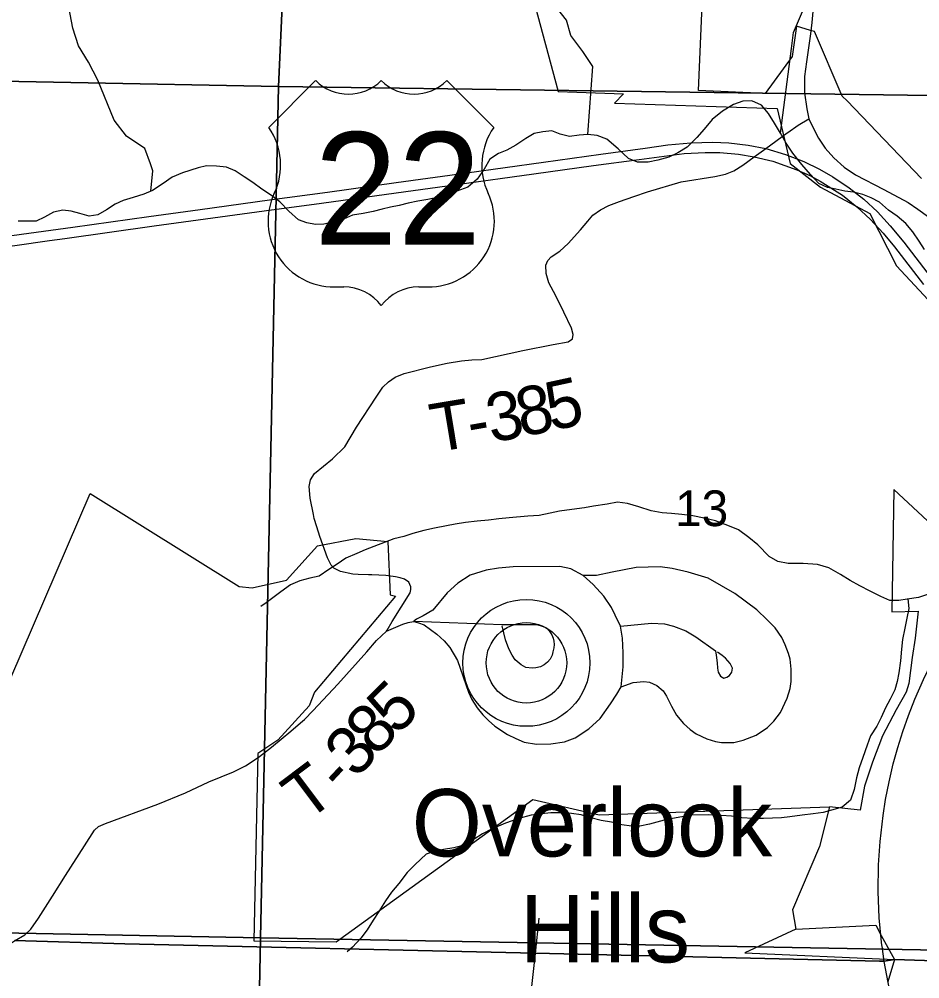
# Model space of a CAD drawing. Extents: x -19 to 40.8, y -1.8 to 26.1.
# Drawn here: x 7.005 to 8.061, y 15.876 to 17.001 of the extents above; entities that cross this region are included whole.
import ezdxf

# ---------------------------------------------------------------- set-up
doc = ezdxf.new("R2010")
doc.units = 0
for name, color, linetype in [('Default', 7, 'Continuous'), ('GM_X_City_Street', 7, 'Continuous'), ('GM_X_Corporation', 7, 'Continuous'), ('GM_X_Corporation_Text', 7, 'Continuous'), ('GM_X_Major_River', 7, 'Continuous'), ('GM_X_Rail_Line_Text', 7, 'Continuous'), ('GM_X_Section', 7, 'Continuous'), ('GM_X_Section_Text', 7, 'Continuous'), ('GM_X_State_Route', 7, 'Continuous'), ('GM_X_State_Shield', 7, 'Continuous'), ('GM_X_Township_Road', 7, 'Continuous'), ('GM_X_Township_Road_Text', 7, 'Continuous'), ('GM_X_Unincorporated', 7, 'Continuous'), ('GM_X_Unincorporated_Location', 7, 'Continuous'), ('RW_P_Text', 7, 'Continuous')]:
    doc.layers.add(name, color=color, linetype=linetype)

msp = doc.modelspace()

# ---------------------------------------------------------------- linework, layer by layer
at = {"layer": 'Default'}
for p, q in [((7.5751, 17.147), (7.6369, 16.9157)), ((7.8016, 16.917), (7.8065, 17.0357)), ((7.9164, 16.9926), (7.9112, 16.957)), ((7.9326, 16.9875), (7.9164, 16.9926)), ((7.9375, 16.986), (7.9326, 16.9875)), ((7.9699, 16.9105), (7.9375, 16.986)), ((7.9112, 16.957), (7.8798, 16.9137)), ((7.6369, 16.9157), (7.7134, 16.913)), ((7.7134, 16.913), (7.7029, 16.902)), ((7.8798, 16.9137), (7.8016, 16.917)), ((7.9759, 16.9049), (7.9699, 16.9105)), ((7.7029, 16.902), (7.8935, 16.8961)), ((7.8935, 16.8961), (7.9088, 16.8316)), ((8.0628, 16.814), (7.9759, 16.9049)), ((7.9088, 16.8316), (7.9446, 16.8036)), ((7.9446, 16.8036), (8.0023, 16.7729)), ((8.0023, 16.7729), (8.0335, 16.7116)), ((8.0335, 16.7116), (8.1315, 16.6064)), ((8.0306, 16.4492), (8.028, 16.3061)), ((8.107, 16.3778), (8.0306, 16.4492)), ((8.028, 16.3061), (8.0591, 16.3066)), ((8.0591, 16.3066), (8.0554, 16.275)), ((8.0554, 16.275), (8.0521, 16.2524)), ((8.0521, 16.2524), (8.048, 16.2219)), ((8.048, 16.2219), (8.045, 16.2119)), ((8.045, 16.2119), (8.0334, 16.1909)), ((8.0334, 16.1909), (8.0171, 16.1606)), ((8.0171, 16.1606), (8.0055, 16.1298)), ((8.0055, 16.1298), (7.996, 16.1017)), ((7.996, 16.1017), (7.991, 16.0734)), ((7.9552, 16.0772), (7.9432, 16.0309)), ((7.991, 16.0734), (7.9552, 16.0772)), ((7.9432, 16.0309), (7.9117, 15.9566)), ((7.9117, 15.9566), (7.9157, 15.9341)), ((7.9157, 15.9341), (8.0093, 15.9388)), ((8.0093, 15.9388), (8.0155, 15.9265)), ((8.0155, 15.9265), (8.0312, 15.8982)), ((8.0312, 15.8982), (8.0236, 15.8722))]:
    msp.add_line(p, q, dxfattribs=at)
at = {"layer": 'GM_X_City_Street'}
msp.add_lwpolyline([(6.995, 16.2287), (7.0882, 16.4448), (7.263, 16.3356), (7.2781, 16.3341), (7.3184, 16.3429), (7.3546, 16.3832), (7.3995, 16.3917), (7.4373, 16.3885), (7.4401, 16.3259), (7.4463, 16.3244), (7.3512, 16.2118), (7.345, 16.1959), (7.308, 16.1556), (7.2849, 16.14), (7.2802, 15.9203), (7.3765, 15.9189), (7.6072, 16.0861), (7.685, 16.0681), (7.9552, 16.0772), (7.9432, 16.0309), (7.9117, 15.9566), (7.9157, 15.9341), (7.8559, 15.9062), (8.0312, 15.8982), (8.0236, 15.8722)], dxfattribs=at)
at = {"layer": 'GM_X_Corporation'}
msp.add_line((8.0166, 15.9149), (8.0146, 15.935), dxfattribs=at)
for points in [[(7.9966, 17.4133), (8.0089, 17.3477), (8.0139, 17.3164), (8.0122, 17.3002), (8.0046, 17.2819), (7.9939, 17.261), (7.9865, 17.2479), (7.9767, 17.2334), (7.9567, 17.2069), (7.944, 17.1887), (7.9394, 17.1801), (7.936, 17.172), (7.9339, 17.1618), (7.9338, 17.1515), (7.9356, 17.1389), (7.9405, 17.1086), (7.9411, 17.0777), (7.9379, 17.0363), (7.9343, 16.9966), (7.9326, 16.9836)], [(7.9326, 16.9836), (7.9282, 16.9507), (7.9259, 16.9335), (7.9256, 16.9143), (7.9283, 16.8957), (7.931, 16.884)], [(7.931, 16.884), (7.9351, 16.8747), (7.942, 16.8613), (7.95, 16.8493), (7.96, 16.838), (7.9721, 16.8271), (7.9856, 16.818), (8.0186, 16.8008), (8.0471, 16.7858), (8.0586, 16.7781), (8.071, 16.7688)], [(8.0146, 15.935), (8.0134, 15.9471), (8.0121, 15.9781), (8.0125, 16.0094), (8.0143, 16.0368), (8.0178, 16.0672), (8.0207, 16.0859), (8.0249, 16.1068), (8.0298, 16.1277), (8.0351, 16.1467), (8.0412, 16.1656), (8.0476, 16.1845), (8.0551, 16.2034), (8.0653, 16.2266), (8.0744, 16.2452), (8.0881, 16.2703), (8.0996, 16.2893), (8.114, 16.3108), (8.1181, 16.3165)], [(8.0252, 15.8656), (8.0238, 15.8716), (8.0193, 15.896), (8.0167, 15.9139), (8.0166, 15.9149)]]:
    msp.add_lwpolyline(points, dxfattribs=at)
at = {"layer": 'GM_X_Major_River'}
msp.add_line((7.5997, 16.2461), (7.5997, 16.2461), dxfattribs=at)
at = {"layer": 'GM_X_Rail_Line_Text'}
msp.add_lwpolyline([(7.5946, 15.6548), (7.5902, 15.6697), (7.5874, 15.6829), (7.5891, 15.7052), (7.594, 15.7458), (7.6004, 15.8125), (7.6061, 15.8669), (7.6103, 15.9053), (7.6148, 15.947)], dxfattribs=at)
at = {"layer": 'GM_X_Section'}
for points in [[(7.1594, 16.7991), (7.1616, 16.8229), (7.1588, 16.8312), (7.1521, 16.849), (7.1307, 16.8634), (7.1163, 16.8822), (7.097, 16.929), (7.086, 16.9501), (7.0743, 16.9693), (7.0679, 16.9901), (7.0604, 17.0295), (7.0556, 17.0458), (7.05, 17.0605), (7.0456, 17.0756), (7.0397, 17.0907), (7.0298, 17.1156), (7.0228, 17.1459), (7.018, 17.1637), (7.0112, 17.1792), (7.0087, 17.1943), (7.0059, 17.2034), (7.0017, 17.2041)], [(7.6717, 16.8656), (7.6777, 16.945), (7.6657, 16.9626), (7.6517, 16.9814), (7.6465, 16.9996), (7.6132, 17.0423)], [(7.8975, 16.8669), (7.9105, 16.9662), (7.9129, 16.9852), (7.9303, 17.0266)], [(7.8975, 16.8669), (7.8906, 16.8788), (7.8834, 16.89), (7.8752, 16.8997), (7.864, 16.905), (7.8533, 16.9047), (7.8424, 16.9006), (7.8294, 16.8929), (7.8175, 16.8831), (7.808, 16.8717), (7.7995, 16.862), (7.7881, 16.8506), (7.7773, 16.8438), (7.7668, 16.8389), (7.7536, 16.8355), (7.7423, 16.8332), (7.7301, 16.8332), (7.7193, 16.8374), (7.7072, 16.8485), (7.6939, 16.8598), (7.6828, 16.8644), (7.6717, 16.8656), (7.6615, 16.8645), (7.6501, 16.8631), (7.6394, 16.8658), (7.6294, 16.8696), (7.6191, 16.8686), (7.6089, 16.8667), (7.5989, 16.8607), (7.5873, 16.8531), (7.5768, 16.8471), (7.5671, 16.843), (7.5566, 16.8366), (7.5502, 16.825), (7.5418, 16.8129), (7.5311, 16.8039), (7.5093, 16.796), (7.4968, 16.7921), (7.484, 16.7891), (7.4723, 16.7872), (7.4609, 16.7849), (7.4504, 16.7823), (7.4402, 16.7801), (7.4304, 16.7779), (7.4198, 16.7753), (7.4081, 16.773), (7.3956, 16.7708), (7.3817, 16.7646), (7.3621, 16.7602), (7.3522, 16.7599), (7.3423, 16.7619), (7.3323, 16.7654), (7.3209, 16.7757), (7.3107, 16.7867), (7.3006, 16.794), (7.2893, 16.8013), (7.2788, 16.8093), (7.2687, 16.8159), (7.2583, 16.8227), (7.2479, 16.827), (7.2364, 16.8285), (7.2246, 16.8289), (7.2148, 16.8263), (7.1964, 16.8204), (7.1844, 16.8155), (7.1739, 16.8079), (7.1613, 16.7999), (7.1511, 16.7955), (7.1387, 16.7916), (7.127, 16.7882), (7.1173, 16.7837), (7.1072, 16.777), (7.0972, 16.7713), (7.0869, 16.7699), (7.0762, 16.773), (7.0658, 16.7757), (7.0559, 16.7769), (7.045, 16.7746), (7.0345, 16.7686), (7.0248, 16.7637), (7.0153, 16.7638), (7.0039, 16.7639)], [(8.0664, 16.7307), (8.06, 16.7404), (8.0528, 16.7512), (8.0445, 16.7612), (8.0343, 16.7696), (8.0242, 16.7769), (8.0137, 16.7861), (8.004, 16.7911), (7.994, 16.7953), (7.9833, 16.7977), (7.973, 16.7989), (7.9623, 16.8012), (7.9527, 16.8032), (7.9427, 16.8082), (7.9328, 16.8186), (7.9226, 16.8304), (7.9119, 16.8434), (7.9043, 16.8553), (7.8975, 16.8669)], [(8.0711, 16.3266), (8.0594, 16.3229), (8.0462, 16.3209), (8.0363, 16.3191), (8.0257, 16.3192), (8.0153, 16.3238), (8.0029, 16.3302), (7.9905, 16.3363), (7.9793, 16.3428), (7.9681, 16.3497), (7.9542, 16.3573), (7.9411, 16.3614), (7.924, 16.3624), (7.9065, 16.3626), (7.8946, 16.3649), (7.8845, 16.3707), (7.8712, 16.3844), (7.8606, 16.3932), (7.8482, 16.4019), (7.8359, 16.4072), (7.8213, 16.4125), (7.8079, 16.4159), (7.7948, 16.4185), (7.7819, 16.42), (7.7697, 16.4211), (7.759, 16.422), (7.746, 16.4242), (7.7314, 16.4291), (7.718, 16.4329), (7.7065, 16.4344), (7.6944, 16.4321), (7.6782, 16.4297), (7.6679, 16.4279), (7.6528, 16.4259), (7.6384, 16.4239), (7.6275, 16.4217), (7.6146, 16.419), (7.6013, 16.4182), (7.5794, 16.416), (7.5672, 16.4149), (7.5551, 16.4134), (7.5418, 16.4122), (7.5282, 16.4106), (7.5161, 16.4087), (7.5059, 16.4069), (7.4919, 16.4038), (7.4795, 16.4011), (7.4666, 16.3977), (7.4561, 16.3943), (7.4444, 16.3913), (7.4339, 16.3876), (7.4207, 16.3826), (7.4106, 16.3785), (7.4008, 16.3744), (7.3881, 16.3687), (7.3777, 16.3619), (7.368, 16.3555), (7.3568, 16.3479), (7.3459, 16.3453), (7.3338, 16.3423), (7.3229, 16.3374), (7.3118, 16.3294), (7.2947, 16.3163), (7.2884, 16.3123)], [(8.0469, 16.321), (8.048, 16.31), (8.0457, 16.2985), (8.0434, 16.2866), (8.0408, 16.2736), (8.0396, 16.2622), (8.0385, 16.2485), (8.0363, 16.2343), (8.0344, 16.2244), (8.0316, 16.2144), (8.0263, 16.2036), (8.0209, 16.1932), (8.0155, 16.182), (8.0105, 16.1719), (8.0033, 16.1607), (7.9991, 16.1495), (7.9942, 16.1353), (7.99, 16.123), (7.9866, 16.1115), (7.984, 16.0977), (7.9798, 16.0851), (7.9698, 16.0768), (7.9574, 16.0734), (7.9476, 16.0708), (7.9358, 16.0693), (7.923, 16.0677), (7.9086, 16.0658), (7.8987, 16.0643), (7.8775, 16.0637), (7.8653, 16.0637), (7.8523, 16.0644), (7.8401, 16.0663), (7.8279, 16.0671), (7.8127, 16.0681), (7.7933, 16.0675), (7.782, 16.0657), (7.771, 16.0638), (7.7612, 16.0616), (7.7439, 16.0569), (7.7325, 16.0546), (7.723, 16.0547), (7.7116, 16.0563), (7.6993, 16.0593), (7.6875, 16.0612), (7.6752, 16.0643), (7.664, 16.0681), (7.6526, 16.0697), (7.64, 16.0704), (7.6282, 16.0704), (7.6172, 16.0693), (7.6051, 16.0674), (7.5908, 16.0636), (7.575, 16.0581), (7.5596, 16.0516), (7.548, 16.0455), (7.5383, 16.0395), (7.5268, 16.0323), (7.5147, 16.0293), (7.5026, 16.0274), (7.4924, 16.0252), (7.4823, 16.0218), (7.4693, 16.0096), (7.4597, 16.0002), (7.4499, 15.9873), (7.4415, 15.9772), (7.4346, 15.9671), (7.4266, 15.9547), (7.4201, 15.9446), (7.4128, 15.933), (7.4055, 15.9232), (7.3956, 15.913), (7.3893, 15.9075)]]:
    msp.add_lwpolyline(points, dxfattribs=at)
at = {"layer": 'GM_X_State_Route'}
for points in [[(6.9993, 15.9207), (7.1288, 15.9169), (7.6101, 15.9059), (8.0135, 15.8966), (8.0191, 15.8965), (8.0312, 15.8982), (8.1843, 15.8933), (8.1919, 15.8932), (8.7332, 15.8828), (8.7397, 15.8827), (8.8013, 15.8813), (8.8296, 15.8807), (8.9, 15.8791), (8.9, 20.9)], [(7.9062, 16.8679), (7.9182, 16.8764), (7.931, 16.884)], [(7.7257, 16.7927), (7.7416, 16.7983), (7.7811, 16.81), (7.8206, 16.8162), (7.8331, 16.8189), (7.8428, 16.8228), (7.8536, 16.8294), (7.8669, 16.8392), (7.8803, 16.849), (7.9054, 16.8673), (7.9062, 16.8679)], [(7.354, 16.4057), (7.3509, 16.4153), (7.35, 16.42), (7.3462, 16.4391), (7.3449, 16.4527), (7.3465, 16.4605), (7.3513, 16.468), (7.3723, 16.4854), (7.3868, 16.4992), (7.4004, 16.5225), (7.4234, 16.5577), (7.4315, 16.5693), (7.4378, 16.5754), (7.4458, 16.5811), (7.4565, 16.5853), (7.4871, 16.5931), (7.5067, 16.5975), (7.5236, 16.6002), (7.5357, 16.6012), (7.5472, 16.6018), (7.5956, 16.6124), (7.6311, 16.6194), (7.6486, 16.6224), (7.6536, 16.626), (7.6546, 16.6309), (7.6527, 16.6385), (7.6434, 16.6573), (7.634, 16.6762), (7.6261, 16.6917), (7.6229, 16.7026), (7.6225, 16.7121), (7.6249, 16.7176), (7.6288, 16.7222), (7.6389, 16.7287), (7.6488, 16.7377), (7.6629, 16.7536), (7.6716, 16.764), (7.6777, 16.7709), (7.6865, 16.7772), (7.6965, 16.7824), (7.7088, 16.7868), (7.7257, 16.7927)], [(7.4185, 16.3491), (7.4145, 16.3493), (7.4023, 16.3498), (7.3962, 16.3501), (7.3817, 16.3532), (7.3739, 16.3572), (7.3707, 16.3608), (7.3666, 16.3691), (7.3576, 16.3942), (7.354, 16.4057)], [(7.4358, 16.2834), (7.4546, 16.2916), (7.4609, 16.2936), (7.4672, 16.2946), (7.4675, 16.2946), (7.4733, 16.2932), (7.4799, 16.2907), (7.4946, 16.2798), (7.5031, 16.272), (7.5099, 16.264), (7.5187, 16.2488), (7.5316, 16.2117), (7.5358, 16.2032), (7.5419, 16.1935), (7.5487, 16.1852), (7.5552, 16.1787), (7.5625, 16.1717), (7.5775, 16.162), (7.5872, 16.1575), (7.5972, 16.1533), (7.6115, 16.1507), (7.6282, 16.1511), (7.6443, 16.1537), (7.6568, 16.1582), (7.673, 16.1686), (7.6861, 16.1809), (7.6983, 16.1979), (7.7055, 16.2095), (7.7109, 16.2179), (7.7248, 16.2229), (7.7374, 16.2244), (7.7439, 16.2235), (7.7527, 16.2196), (7.7602, 16.2133), (7.7639, 16.2072), (7.7698, 16.1954), (7.7755, 16.1847), (7.7838, 16.1751), (7.7918, 16.168), (7.7989, 16.163), (7.8111, 16.1571), (7.8213, 16.1539), (7.8286, 16.1529), (7.843, 16.1528), (7.8538, 16.1554), (7.869, 16.1613), (7.8824, 16.1702), (7.8899, 16.1777), (7.8977, 16.1879), (7.9053, 16.2049), (7.909, 16.2161), (7.9102, 16.2244), (7.9102, 16.2387), (7.9089, 16.2506), (7.9069, 16.2569), (7.9032, 16.2673), (7.8991, 16.276), (7.8913, 16.2871), (7.8821, 16.2967), (7.8697, 16.3081), (7.8442, 16.3276), (7.8126, 16.3455), (7.7894, 16.3524), (7.7704, 16.3568), (7.7564, 16.3586), (7.7284, 16.3578), (7.7001, 16.3524), (7.6818, 16.3486), (7.6662, 16.3485), (7.6517, 16.3565), (7.6387, 16.3589), (7.5842, 16.3587), (7.5671, 16.3571), (7.5523, 16.3549), (7.5339, 16.3489), (7.5193, 16.3395), (7.5067, 16.3281), (7.4898, 16.3079), (7.4786, 16.3011), (7.4707, 16.2974), (7.4676, 16.2949)], [(7.4363, 16.2843), (7.4424, 16.2947), (7.4634, 16.328), (7.4642, 16.3319), (7.4641, 16.3353), (7.4616, 16.3405), (7.4569, 16.3442), (7.4516, 16.3458), (7.4463, 16.3468), (7.4347, 16.3486), (7.4185, 16.3491)], [(7.7109, 16.2179), (7.713, 16.2415), (7.7133, 16.258), (7.7122, 16.2751), (7.71, 16.2891), (7.7038, 16.3021), (7.6996, 16.3109), (7.6903, 16.3243), (7.678, 16.3378), (7.6662, 16.3485)], [(7.4676, 16.2949), (7.5712, 16.2909), (7.5849, 16.291), (7.6118, 16.2911), (7.618, 16.2892), (7.6233, 16.287), (7.6264, 16.2836), (7.6295, 16.2789), (7.6309, 16.2751), (7.632, 16.2717), (7.6321, 16.2677), (7.632, 16.2639), (7.6308, 16.2591), (7.6297, 16.2552), (7.6274, 16.2505), (7.6245, 16.247), (7.6205, 16.2439), (7.6161, 16.2415), (7.6108, 16.2403), (7.6065, 16.2399), (7.599, 16.2408), (7.5937, 16.2439), (7.5866, 16.2498), (7.5831, 16.2552), (7.579, 16.2624), (7.5751, 16.2731), (7.5713, 16.2894)], [(7.71, 16.2891), (7.7464, 16.2926), (7.7614, 16.2918), (7.772, 16.2892), (7.7867, 16.2836), (7.7985, 16.2767), (7.8212, 16.2603), (7.8221, 16.2553), (7.8235, 16.2461), (7.8238, 16.2399), (7.8245, 16.2351), (7.8272, 16.2304), (7.8311, 16.2283), (7.8347, 16.2294), (7.8377, 16.2313), (7.8406, 16.2351), (7.8414, 16.2399), (7.8387, 16.2455), (7.8332, 16.2516), (7.8292, 16.2547), (7.8238, 16.2587)], [(7.3349, 16.1759), (7.3394, 16.1798), (7.3495, 16.1901), (7.3786, 16.221), (7.4126, 16.2589), (7.4238, 16.2724), (7.4358, 16.2834), (7.4363, 16.2843)], [(7.2721, 16.1264), (7.2866, 16.1364), (7.3009, 16.1473), (7.3235, 16.1662), (7.3349, 16.1759)], [(6.9776, 15.8996), (6.9843, 15.9053), (6.9891, 15.912), (6.9934, 15.9162), (6.9982, 15.9194), (6.9995, 15.9202), (7.0114, 15.9273), (7.0186, 15.934), (7.0277, 15.9467), (7.044, 15.9727), (7.0593, 15.9969), (7.0813, 16.0315), (7.0933, 16.0501), (7.098, 16.0543), (7.106, 16.0577), (7.1676, 16.0804), (7.1999, 16.0937), (7.2273, 16.1065), (7.2561, 16.1185), (7.2704, 16.1253), (7.2721, 16.1264)], [(4.3215, 14.1), (8.9, 14.1), (8.9, 15.8791), (8.8296, 15.8807), (8.8013, 15.8813), (8.7397, 15.8827), (8.7332, 15.8828), (8.1919, 15.8932), (8.1843, 15.8933), (8.0312, 15.8982), (8.0191, 15.8965), (8.0135, 15.8966), (7.6101, 15.9059), (7.1288, 15.9169), (6.9993, 15.9207)]]:
    msp.add_lwpolyline(points, dxfattribs=at)
at = {"layer": 'GM_X_State_Shield'}
for p, q in [((7.3525, 16.9286), (7.2976, 16.8736)), ((7.5613, 16.8736), (7.5063, 16.9286)), ((7.3745, 16.6869), (7.3855, 16.6869)), ((7.4734, 16.6869), (7.4844, 16.6869))]:
    msp.add_line(p, q, dxfattribs=at)
for centre, radius, start, end in [((7.391, 16.9678), 0.0549, 225.573, 314.427), ((7.4679, 16.9678), 0.0549, 225.573, 314.427), ((7.2346, 16.8295), 0.0769, 334.5471, 35.0009), ((7.6243, 16.8295), 0.0769, 144.9991, 205.4529), ((7.3736, 16.7638), 0.0769, 154.8319, 270.6383), ((7.4852, 16.7638), 0.0769, 269.3617, 25.1681), ((7.3855, 16.6319), 0.0549, 36.8699, 90), ((7.4734, 16.6319), 0.0549, 90, 143.1301)]:
    msp.add_arc(centre, radius, start, end, dxfattribs=at)
at = {"layer": 'GM_X_Township_Road'}
for points in [[(6.9395, 16.7394), (7.0077, 16.7487), (7.0677, 16.7569), (7.1568, 16.7693), (7.217, 16.7776), (7.2984, 16.789), (7.3665, 16.798), (7.4468, 16.8091), (7.5298, 16.8206), (7.6197, 16.8331), (7.687, 16.8423), (7.7391, 16.8496), (7.7655, 16.8532), (7.7923, 16.8557), (7.8181, 16.8565), (7.8369, 16.8556), (7.8595, 16.8528), (7.8803, 16.849), (7.9034, 16.842), (7.9249, 16.8337), (7.9434, 16.8249), (7.959, 16.8158), (7.9782, 16.8031), (7.9952, 16.7895), (8.0112, 16.7748), (8.0261, 16.7585), (8.0423, 16.7392), (8.0744, 16.6976)], [(7.0406, 16.7411), (7.0585, 16.7436), (7.1633, 16.7584), (7.2923, 16.7761), (7.3593, 16.7849), (7.4356, 16.7955), (7.518, 16.8068), (7.6082, 16.8193), (7.6783, 16.829), (7.7317, 16.8363), (7.7845, 16.843), (7.8093, 16.8445), (7.8264, 16.8442), (7.8482, 16.8423), (7.8669, 16.8392), (7.8885, 16.834), (7.9167, 16.8242), (7.9318, 16.8174), (7.9442, 16.8106), (7.9702, 16.7943), (7.9872, 16.7807), (8.0032, 16.766), (8.0181, 16.7498), (8.0313, 16.7337), (8.0654, 16.6898)], [(6.8202, 16.7189), (6.8223, 16.7189), (6.847, 16.7198), (6.8933, 16.7224), (6.9304, 16.7262), (6.9998, 16.7354), (7.0406, 16.7411)]]:
    msp.add_lwpolyline(points, dxfattribs=at)
at = {"layer": 'GM_X_Unincorporated'}
for radius in [0.0744, 0.0472]:
    msp.add_circle((7.5997, 16.2461), radius, dxfattribs=at)
at = {"layer": 'RW_P_Text'}
for points in [[(6.3691, 17.9545), (7.3559, 17.9489), (7.309, 16.9219), (6.3345, 16.9403)], [(7.3559, 17.9489), (8.3666, 17.9389), (8.3301, 16.9076), (7.309, 16.9219)], [(7.309, 16.9219), (7.2877, 15.9238), (6.2953, 15.9429), (6.3345, 16.9403)], [(8.3301, 16.9076), (8.2983, 15.9055), (7.2877, 15.9238), (7.309, 16.9219)], [(6.2953, 15.9429), (7.2877, 15.9238), (7.2668, 14.8526), (6.2831, 14.8757)], [(7.2877, 15.9238), (8.2983, 15.9055), (8.2842, 14.8321), (7.2668, 14.8526)]]:
    msp.add_lwpolyline(points, close=True, dxfattribs=at)

# ---------------------------------------------------------------- texts
at = {"layer": 'GM_X_Corporation_Text'}
for s, p in [('Overlook', (7.4653, 16.0192)), ('Hills', (7.5919, 15.895))]:
    msp.add_text(s, height=0.07898, rotation=0, dxfattribs=at).set_placement(p)
at = {"layer": 'GM_X_Section_Text'}
msp.add_text('13', height=0.04186, rotation=0, dxfattribs=at).set_placement((7.774, 16.4064))
at = {"layer": 'GM_X_State_Shield'}
msp.add_text('22', height=0.13184, dxfattribs=at).set_placement((7.3507, 16.7363))
at = {"layer": 'GM_X_Township_Road_Text'}
for s, rotation, p in [('5', 12.2297, (7.6287, 16.5178)), ('8', 11.5264, (7.5937, 16.5107)), ('3', 10.7114, (7.5584, 16.504)), ('T', 9.4236, (7.4921, 16.4927)), ('-', 9.9792, (7.5347, 16.4998)), ('5', 44.4995, (7.4473, 16.16)), ('8', 46.5899, (7.4236, 16.135)), ('3', 47.7126, (7.4002, 16.1093)), ('T', 36.9033, (7.3417, 16.0589)), ('-', 46.9925, (7.3838, 16.0917))]:
    msp.add_text(s, height=0.0568, rotation=rotation, dxfattribs=at).set_placement(p)
at = {"layer": 'GM_X_Unincorporated_Location'}
for s in ['0', '/']:
    msp.add_text(s, height=0.000189, dxfattribs=at).set_placement((7.4294, 16.8012))
msp.add_text('22', height=0.000189, rotation=0, dxfattribs=at).set_placement((7.3903, 16.762))

doc.saveas('drawing.dxf')
